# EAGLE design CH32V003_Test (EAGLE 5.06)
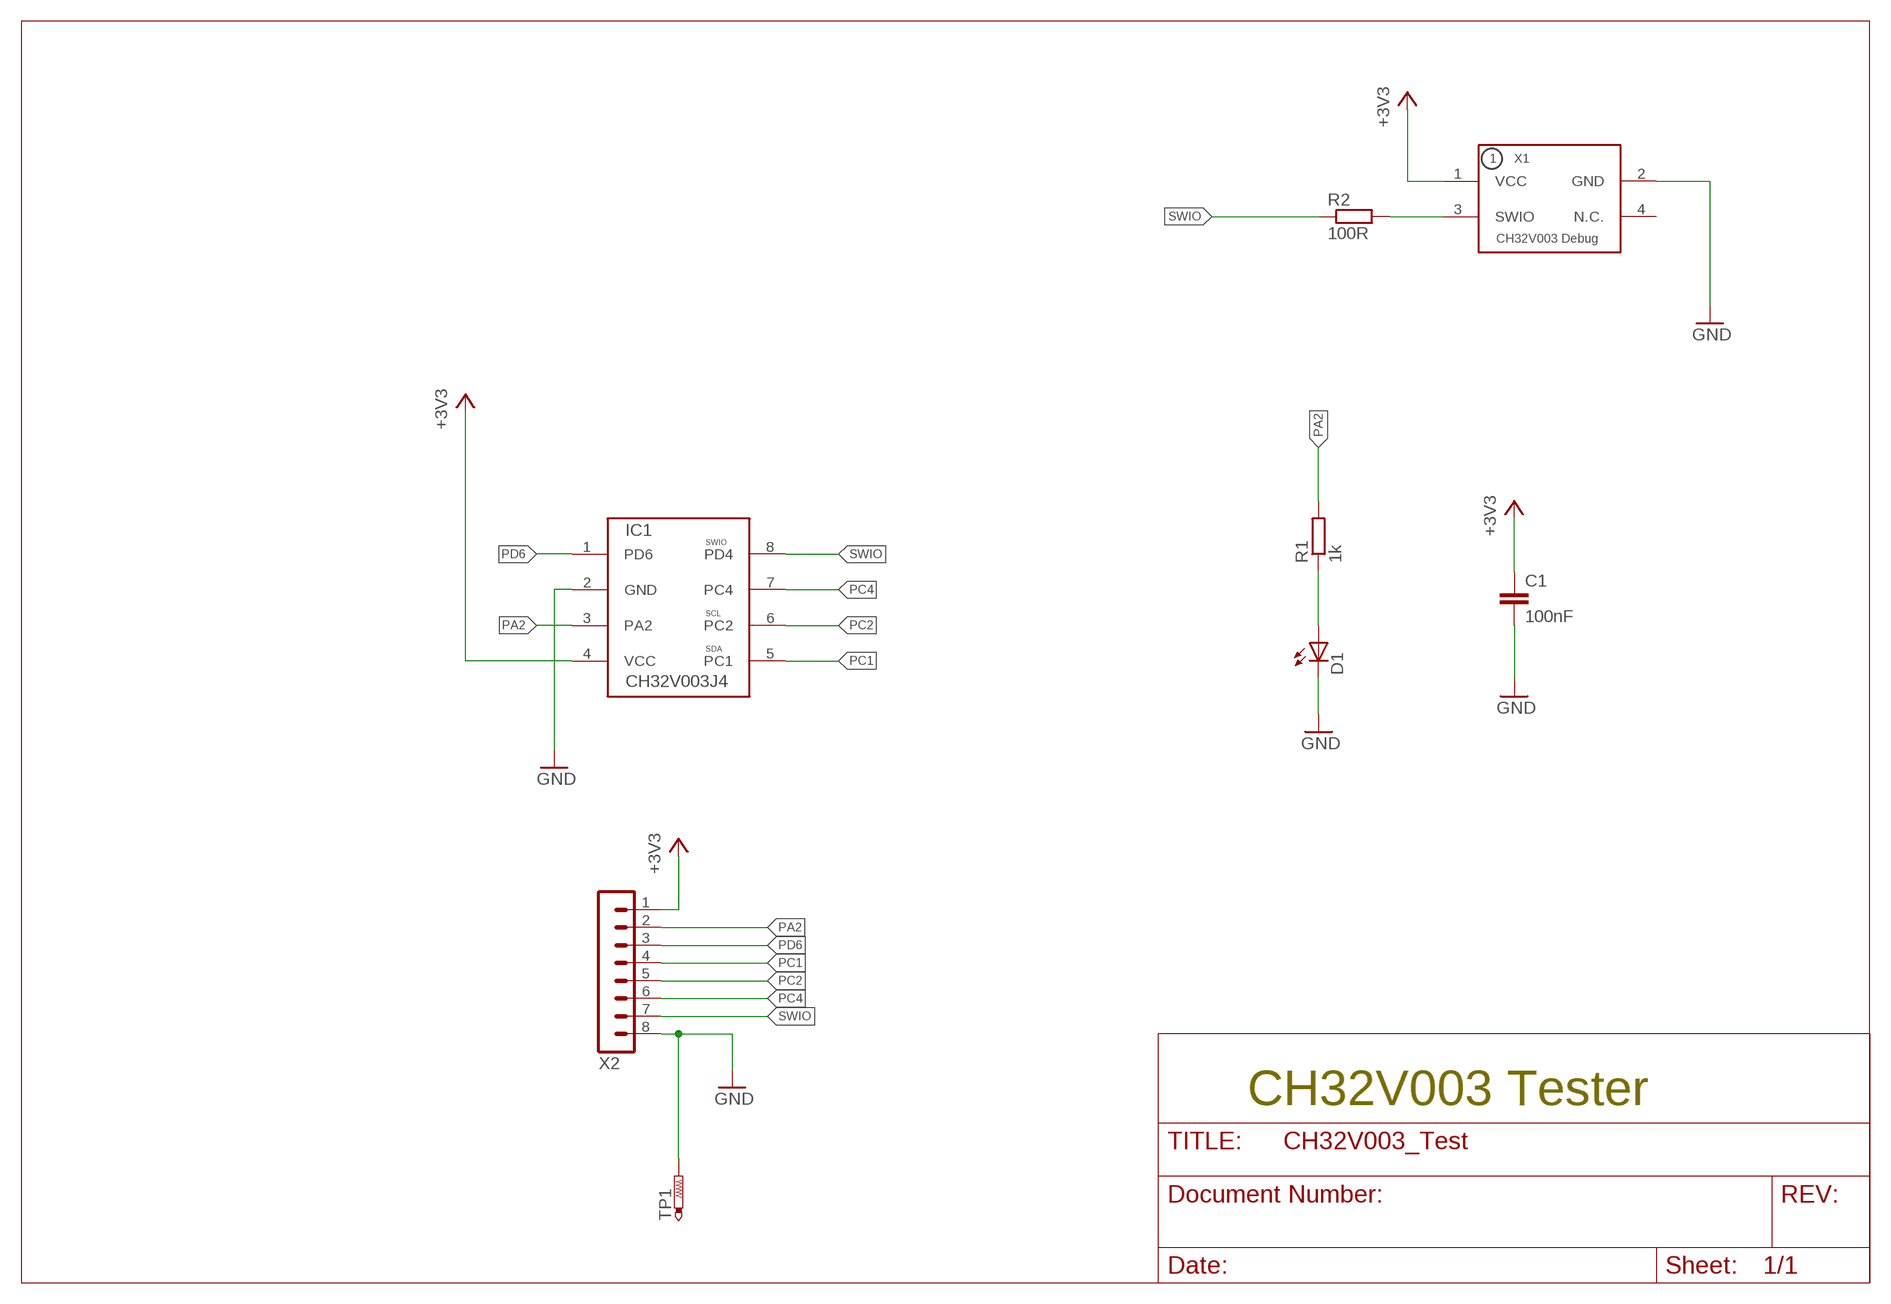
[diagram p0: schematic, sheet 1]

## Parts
C1  100nF  C-EUC0603  [C0603]
D1  LEDCHIP-LED0603  [CHIP-LED0603]
IC1  CH32V003J4M6  [SO8]
R1  1k  R-EU_R0603  [R0603]
R2  100R  R-EU_R0603  [R0603]
TP1  GND  TEST_OESE  [TEST_HAKEN]
X1  CH32V003_DEBUG  [CH32V003_DEBUG]
X2  MA08-1W  [MA08-1W]

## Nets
+3V3: C1.1 IC1.4(VCC) X1.1(VCC) X2.1
GND: C1.2 D1.C IC1.2(GND) TP1.P$1(TP) X1.2(GND) X2.8
N$1: R2.2 X1.3(SWIO)
N$2: D1.A R1.1
PA2: IC1.3(PA2) R1.2 X2.2
PC1: IC1.5(PC1) X2.4
PC2: IC1.6(PC2) X2.5
PC4: IC1.7(PC4) X2.6
PD6: IC1.1(PD6) X2.3
SWIO: IC1.8(PD4) R2.1 X2.7
Unconnected: X1.4(N.C.)

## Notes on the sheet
- CH32V003 Tester

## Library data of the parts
C1 = rcl:C-EU: CAPACITOR, European symbol
D1 = led:LED: LED
IC1 = olaf_V5:CH32V003J4M6: Risc/V Microcontroller
R1 R2 = rcl:R-EU_: RESISTOR, European symbol
TP1 = olaf_V5:TEST_OESE: Testpunkt fuer den Einsatz einer der Oesen von denen wir 100000Stk haben
X1 = olaf_V5:CH32V003_DEBUG: CH32V003 Debugstecker
X2 = con-lstb:MA08-1W: PIN HEADER

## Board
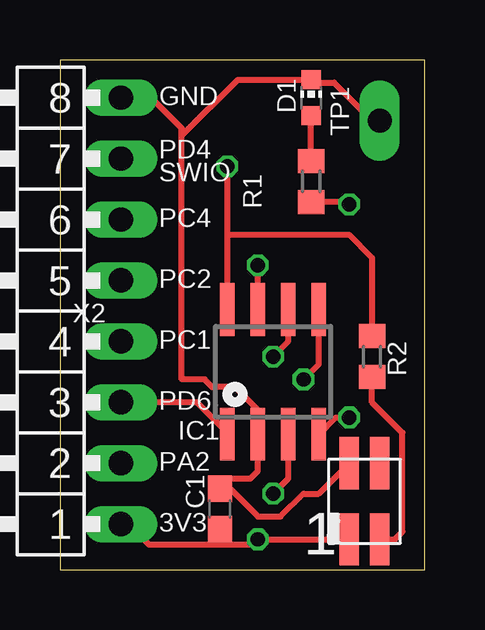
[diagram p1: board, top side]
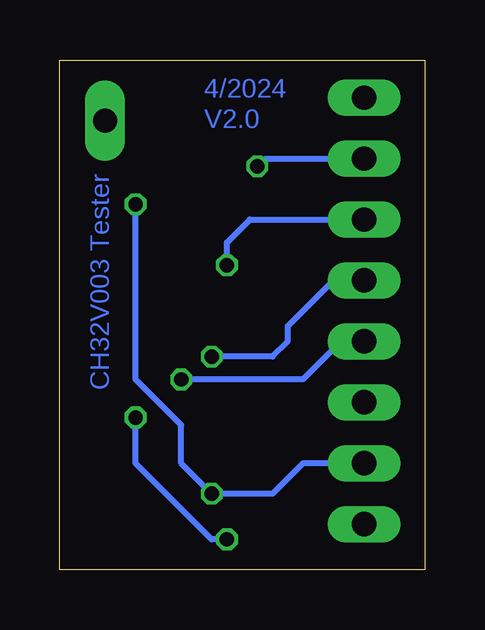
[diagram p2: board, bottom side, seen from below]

Size 15.22 x 21.26 mm. Coordinates in mm from the lower left corner, seen from the top.
Outline: 0,0 15.22,0 15.22,21.26 0,21.26 0,0
Copper layers (1*16): Top 0.035mm / dielectric 1.6mm / Bottom 0.035mm
Design rules "Elecrow_2-layer_PCB_eagle_rule": minimum track width 6mil, minimum drill 12mil, track to track 6mil, track to pad 6mil, pad to pad 6mil, via to via 8mil, smd to smd 0mil, copper to edge 20mil, drill to drill 10mil, minimum pad ring 6mil, minimum via ring 6mil, stop-mask expansion 0mil, vias tented up to drill 100mil, thermal gap 10mil

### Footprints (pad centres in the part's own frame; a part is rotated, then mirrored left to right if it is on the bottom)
C0603 = smd 1.1 x 1: 1 -0.85,0; 2 0.85,0
CHIP-LED0603 = smd 0.8 x 0.8: A 0,-0.75; C 0,0.75
SO8 = smd 0.6 x 2.2: 1 -1.905,-2.6; 2 -0.635,-2.6; 3 0.635,-2.6; 4 1.905,-2.6; 5 1.905,2.6; 6 0.635,2.6; 7 -0.635,2.6; 8 -1.905,2.6
R0603 = smd 1 x 1.1: 1 -0.85,0; 2 0.85,0
TEST_HAKEN = drill 1 pad 1.676 long: P$1 0,0
CH32V003_DEBUG = smd 0.813 x 2.184: 1 -0.635,-1.587; 2 -0.635,1.587; 3 0.635,-1.587; 4 0.635,1.587
MA08-1W = drill 1.016 long: 1 -8.89,0; 2 -6.35,0; 3 -3.81,0; 4 -1.27,0; 5 1.27,0; 6 3.81,0; 7 6.35,0; 8 8.89,0

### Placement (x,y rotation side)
C1  6.67,2.54 90 top
D1  10.48,19.68 0 top
IC1  8.89,8.26 0 top
R1  10.48,16.19 270 top
R2  13.02,8.89 270 top
TP1  13.34,18.73 90 top
X1  12.7,2.86 0 top
X2  2.54,10.79 90 top

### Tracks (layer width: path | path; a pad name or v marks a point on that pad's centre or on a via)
+3V3  (via drill 0.6)
  Top 0.254: 6.67,1.05 3.71,1.05 2.86,1.91 X2.1 | 6.67,1.05 8.26,1.05 v8.26,1.27 X1.1 | 6.67,1.05 C1.1 | IC1.4 11.49,6.35 v12.06,6.35
  Bottom 0.254: v12.06,6.35 12.06,4.45 8.89,1.27 v8.26,1.27
GND
  Top 0.254: 5.08,18.1 5.08,7.94 6.03,7.94 6.35,7.62 7.3,7.62 8.26,6.67 IC1.2 8.26,4.13 7.94,3.81 7.09,3.81 C1.2 7.09,3.39 8.26,2.22 9.21,2.22 10.16,3.17 10.79,3.17 X1.2 | 5.08,18.1 5.08,18.41 3.81,19.68 X2.8 | 5.08,18.1 7.42,20.43 D1.C 10.59,20.32 11.43,20.32 13.02,18.73 TP1.P$1
N$1
  Top 0.254: X1.3 13.97,1.27 14.29,1.59 14.29,5.71 13.02,6.99 R2.2
N$2
  Top 0.254: R1.1 D1.A
PA2  (via drill 0.6)
  Top 0.254: IC1.3 9.53,3.81 v8.89,3.17 | R1.2 11.96,15.34 v12.06,15.24
  Bottom 0.254: X2.2 5.08,4.45 6.35,3.17 v8.89,3.17 10.16,4.45 10.16,6.03 12.06,7.94 v12.06,15.24
PC1  (via drill 0.6)
  Top 0.254: IC1.5 10.79,8.57 v10.16,7.94
  Bottom 0.254: v10.16,7.94 5.08,7.94 3.49,9.53 X2.4
PC2  (via drill 0.6)
  Top 0.254: IC1.6 9.53,9.53 v8.89,8.89
  Bottom 0.254: v8.89,8.89 6.35,8.89 5.71,9.53 5.71,10.16 3.81,12.06 X2.5
PC4  (via drill 0.6)
  Top 0.254: IC1.7 v8.26,12.7
  Bottom 0.254: v8.26,12.7 8.26,13.65 7.3,14.61 X2.6
PD6
  Top 0.254: IC1.1 6.99,5.71 5.71,6.99 X2.3
SWIO  (via drill 0.6)
  Top 0.254: R2.1 13.02,13.02 12.06,13.97 6.99,13.97 | IC1.8 6.99,13.97 | 6.99,13.97 v6.99,16.83
  Bottom 0.254: X2.7 6.67,17.14 v6.99,16.83

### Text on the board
Bottom: 4/2024 | V2.0 | CH32V003 Tester
tNames: GND | PD4 | SWIO | PC4 | PC2 | PC1 | PD6 | PA2 | 3V3 | 1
